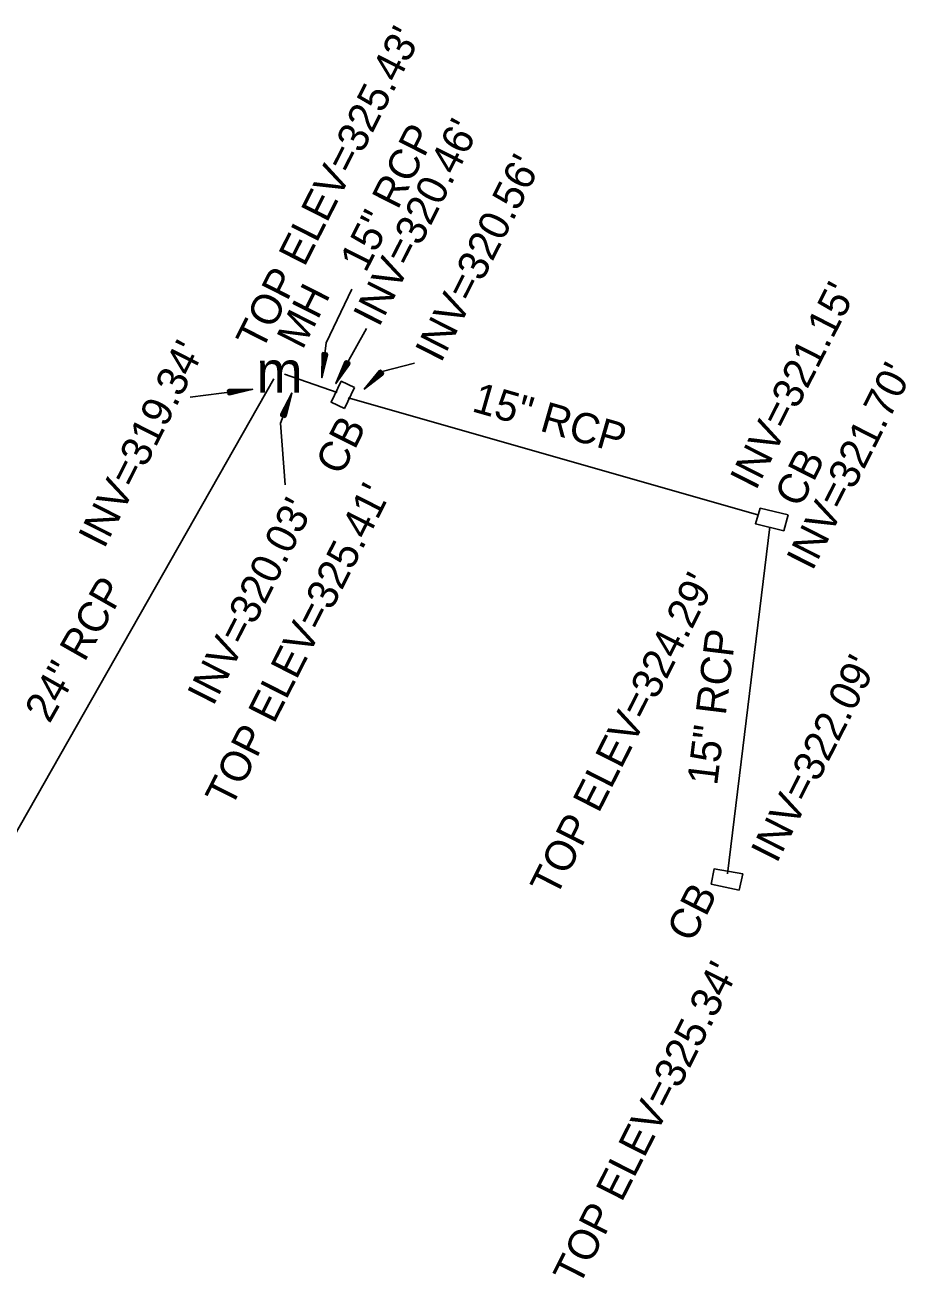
# Model space of a CAD drawing. Extents: x 1975859 to 1978323, y 778892 to 782836.
# Drawn here: x 1978206.4 to 1978322.9, y 782670.7 to 782836.1 of the extents above; entities that cross this region are included whole.
import ezdxf

# ---------------------------------------------------------------- set-up
doc = ezdxf.new("R2010")
doc.units = 0
for name, color, linetype in [('Exist Structure Minor Catch Basin', 7, 'Continuous'), ('Exist Structure Minor Catch Basin Text', 7, 'Continuous'), ('Exist Structure Minor Catch Basin Top Elevation', 7, 'Continuous'), ('Exist Structure Minor Pipes RCP 15 Inch', 7, 'Continuous'), ('Exist Structure Minor Pipes RCP 15 Inch Invert', 7, 'Continuous'), ('Exist Structure Minor Pipes RCP 15 Inch Text', 7, 'Continuous'), ('Exist Structure Minor Pipes RCP 24 Inch', 7, 'Continuous'), ('Exist Structure Minor Pipes RCP 24 Inch Invert', 7, 'Continuous'), ('Exist Structure Minor Pipes RCP 24 Inch Text', 7, 'Continuous'), ('Exist Structure Minor Storm Sewer Manhole CELL', 7, 'Continuous'), ('Exist Structure Minor Storm Sewer Manhole Text', 7, 'Continuous'), ('Exist Structure Minor Storm Sewer Manhole Top Elevation', 7, 'Continuous')]:
    doc.layers.add(name, color=color, linetype=linetype)

msp = doc.modelspace()

# ---------------------------------------------------------------- linework, layer by layer
at = {"layer": 'Exist Structure Minor Catch Basin'}
for p, q in [((1978249.95, 782788.25), (1978248.62, 782785.5)), ((1978307.23, 782771.45), (1978306.66, 782769.34)), ((1978297.06, 782722.69), (1978300.76, 782721.9))]:
    msp.add_line(p, q, dxfattribs=at)
for points in [[(1978249.95, 782788.25), (1978248.2, 782789.1), (1978246.87, 782786.32), (1978248.62, 782785.5)], [(1978306.66, 782769.34), (1978302.9, 782770.27), (1978303.54, 782772.33), (1978307.23, 782771.45)], [(1978300.76, 782721.9), (1978301.23, 782724.04), (1978297.44, 782724.71), (1978297.06, 782722.69)]]:
    msp.add_lwpolyline(points, dxfattribs=at)
at = {"layer": 'Exist Structure Minor Pipes RCP 15 Inch'}
for p, q in [((1978247.65, 782787.62), (1978240.69, 782790.04)), ((1978303.21, 782771.46), (1978249.13, 782786.92)), ((1978299.19, 782724.05), (1978304.79, 782769.85))]:
    msp.add_line(p, q, dxfattribs=at)
at = {"layer": 'Exist Structure Minor Pipes RCP 15 Inch Invert'}
for p, q in [((1978247.49, 782788.78), (1978251.52, 782796.05)), ((1978248.87, 782791.81), (1978249.33, 782791.55)), ((1978248.95, 782791.4), (1978248.89, 782791.74)), ((1978248.95, 782791.4), (1978248.96, 782791.76)), ((1978248.95, 782791.4), (1978249.05, 782791.71)), ((1978248.95, 782791.4), (1978249.15, 782791.65)), ((1978248.95, 782791.4), (1978249.23, 782791.6)), ((1978249.27, 782791.53), (1978248.95, 782791.4)), ((1978253.59, 782790.36), (1978257.88, 782791.49)), ((1978253.38, 782790.16), (1978253.43, 782790.51)), ((1978253.38, 782790.16), (1978253.5, 782790.5)), ((1978253.38, 782790.16), (1978253.57, 782790.42)), ((1978253.38, 782790.16), (1978253.65, 782790.34)), ((1978253.38, 782790.16), (1978253.71, 782790.28)), ((1978253.73, 782790.19), (1978253.38, 782790.16)), ((1978253.42, 782790.57), (1978253.8, 782790.19)), ((1978241.67, 782787.52), (1978240.17, 782783.57)), ((1978240.17, 782783.57), (1978240.78, 782775.43)), ((1978240.74, 782784.32), (1978240.24, 782784.51)), ((1978240.3, 782784.53), (1978240.61, 782784.71)), ((1978240.61, 782784.71), (1978240.36, 782784.47)), ((1978240.61, 782784.71), (1978240.44, 782784.43)), ((1978240.61, 782784.71), (1978240.55, 782784.39)), ((1978240.61, 782784.71), (1978240.71, 782784.38)), ((1978240.61, 782784.71), (1978240.65, 782784.36))]:
    msp.add_line(p, q, dxfattribs=at)
for points in [[(1978248.84, 782791.64), (1978247.49, 782788.78), (1978248.87, 782791.81), (1978248.89, 782791.74), (1978248.84, 782791.64), (1978248.95, 782791.4), (1978249.21, 782791.44), (1978249.27, 782791.53), (1978249.33, 782791.55), (1978247.49, 782788.78), (1978249.21, 782791.44)], [(1978248.87, 782791.81), (1978248.67, 782791.65), (1978247.49, 782788.78), (1978249.3, 782791.3), (1978249.33, 782791.55)], [(1978249.32, 782791.43), (1978247.49, 782788.78), (1978248.77, 782791.73)], [(1978247.59, 782788.92), (1978247.54, 782788.86), (1978247.57, 782788.95), (1978247.61, 782789.03), (1978247.58, 782788.94), (1978247.64, 782789), (1978247.69, 782789.08), (1978247.63, 782789.02), (1978247.65, 782789.11), (1978247.69, 782789.2), (1978247.68, 782789.1), (1978247.74, 782789.16), (1978247.79, 782789.24), (1978247.72, 782789.19), (1978247.73, 782789.28), (1978247.77, 782789.37), (1978247.77, 782789.27), (1978247.84, 782789.32), (1978247.89, 782789.4), (1978247.81, 782789.35), (1978247.81, 782789.45), (1978247.85, 782789.54), (1978247.86, 782789.43), (1978247.94, 782789.47), (1978247.99, 782789.55), (1978247.9, 782789.51), (1978247.89, 782789.62), (1978247.93, 782789.71), (1978247.95, 782789.6), (1978248.04, 782789.63), (1978248.09, 782789.71), (1978247.99, 782789.68), (1978247.97, 782789.79), (1978248.01, 782789.88), (1978248.04, 782789.76), (1978248.15, 782789.79), (1978248.2, 782789.87), (1978248.08, 782789.84), (1978248.05, 782789.96), (1978248.09, 782790.05), (1978248.13, 782789.92), (1978248.25, 782789.95), (1978248.3, 782790.02), (1978248.17, 782790.01), (1978248.13, 782790.13), (1978248.17, 782790.22), (1978248.22, 782790.09), (1978248.35, 782790.1), (1978248.4, 782790.18), (1978248.27, 782790.17), (1978248.21, 782790.3), (1978248.25, 782790.39), (1978248.31, 782790.25), (1978248.45, 782790.26), (1978248.5, 782790.34), (1978248.36, 782790.33), (1978248.29, 782790.47), (1978248.33, 782790.56), (1978248.4, 782790.41), (1978248.55, 782790.42), (1978248.6, 782790.5), (1978248.45, 782790.5), (1978248.37, 782790.64), (1978248.41, 782790.72), (1978248.49, 782790.58), (1978248.65, 782790.58), (1978248.7, 782790.65), (1978248.54, 782790.66), (1978248.45, 782790.81), (1978248.49, 782790.89), (1978248.57, 782790.75), (1978248.75, 782790.73), (1978248.8, 782790.81), (1978248.63, 782790.82), (1978248.53, 782790.98), (1978248.57, 782791.06), (1978248.67, 782790.91), (1978248.86, 782790.89), (1978248.91, 782790.97), (1978248.72, 782790.99), (1978248.61, 782791.15), (1978248.65, 782791.23), (1978248.76, 782791.07), (1978248.96, 782791.05), (1978249.01, 782791.13), (1978248.81, 782791.15), (1978248.69, 782791.32), (1978248.73, 782791.4), (1978248.85, 782791.23), (1978249.06, 782791.2), (1978249.11, 782791.28), (1978248.9, 782791.32), (1978248.77, 782791.49), (1978248.81, 782791.57), (1978248.95, 782791.4), (1978249.16, 782791.36)], [(1978253.36, 782790.42), (1978251.24, 782788.06), (1978253.42, 782790.57), (1978253.43, 782790.51), (1978253.36, 782790.42), (1978253.38, 782790.16), (1978253.65, 782790.12), (1978253.73, 782790.19), (1978253.8, 782790.19), (1978251.24, 782788.06), (1978253.65, 782790.12)], [(1978253.42, 782790.57), (1978253.2, 782790.48), (1978251.24, 782788.06), (1978253.7, 782789.96), (1978253.8, 782790.19)], [(1978253.75, 782790.08), (1978251.24, 782788.06), (1978253.31, 782790.52)], [(1978251.37, 782788.18), (1978251.31, 782788.13), (1978251.36, 782788.2), (1978251.43, 782788.27), (1978251.37, 782788.19), (1978251.44, 782788.24), (1978251.51, 782788.3), (1978251.44, 782788.26), (1978251.49, 782788.34), (1978251.55, 782788.41), (1978251.51, 782788.32), (1978251.59, 782788.36), (1978251.66, 782788.42), (1978251.57, 782788.39), (1978251.61, 782788.48), (1978251.68, 782788.55), (1978251.64, 782788.46), (1978251.73, 782788.48), (1978251.8, 782788.54), (1978251.71, 782788.52), (1978251.74, 782788.62), (1978251.8, 782788.69), (1978251.78, 782788.59), (1978251.87, 782788.6), (1978251.94, 782788.66), (1978251.84, 782788.65), (1978251.86, 782788.76), (1978251.93, 782788.83), (1978251.91, 782788.72), (1978252.01, 782788.72), (1978252.08, 782788.78), (1978251.98, 782788.78), (1978251.99, 782788.9), (1978252.05, 782788.97), (1978252.04, 782788.85), (1978252.15, 782788.85), (1978252.23, 782788.91), (1978252.11, 782788.91), (1978252.11, 782789.04), (1978252.18, 782789.11), (1978252.18, 782788.98), (1978252.3, 782788.97), (1978252.37, 782789.03), (1978252.24, 782789.04), (1978252.24, 782789.18), (1978252.3, 782789.25), (1978252.31, 782789.11), (1978252.44, 782789.09), (1978252.51, 782789.15), (1978252.38, 782789.18), (1978252.37, 782789.32), (1978252.43, 782789.39), (1978252.44, 782789.24), (1978252.58, 782789.21), (1978252.65, 782789.27), (1978252.51, 782789.31), (1978252.49, 782789.46), (1978252.55, 782789.53), (1978252.58, 782789.37), (1978252.72, 782789.33), (1978252.79, 782789.39), (1978252.65, 782789.44), (1978252.61, 782789.6), (1978252.68, 782789.67), (1978252.71, 782789.5), (1978252.87, 782789.45), (1978252.94, 782789.51), (1978252.78, 782789.57), (1978252.74, 782789.74), (1978252.8, 782789.81), (1978252.84, 782789.64), (1978253.01, 782789.58), (1978253.08, 782789.64), (1978252.91, 782789.7), (1978252.87, 782789.87), (1978252.93, 782789.94), (1978252.98, 782789.77), (1978253.15, 782789.7), (1978253.22, 782789.76), (1978253.05, 782789.83), (1978252.99, 782790.01), (1978253.05, 782790.08), (1978253.11, 782789.9), (1978253.29, 782789.82), (1978253.36, 782789.88), (1978253.18, 782789.96), (1978253.12, 782790.15), (1978253.18, 782790.22), (1978253.25, 782790.03), (1978253.43, 782789.94), (1978253.51, 782790), (1978253.31, 782790.09), (1978253.24, 782790.29), (1978253.3, 782790.36), (1978253.38, 782790.16), (1978253.58, 782790.06)], [(1978240.74, 782784.48), (1978241.67, 782787.52), (1978240.74, 782784.32), (1978240.71, 782784.38), (1978240.74, 782784.48), (1978240.61, 782784.71), (1978240.35, 782784.63), (1978240.3, 782784.53), (1978240.24, 782784.51), (1978241.67, 782787.52), (1978240.35, 782784.63)], [(1978240.74, 782784.32), (1978240.91, 782784.5), (1978241.67, 782787.52), (1978240.24, 782784.76), (1978240.24, 782784.51)], [(1978240.24, 782784.63), (1978241.67, 782787.52), (1978240.83, 782784.41)], [(1978241.6, 782787.36), (1978241.63, 782787.43), (1978241.61, 782787.34), (1978241.58, 782787.25), (1978241.6, 782787.34), (1978241.56, 782787.27), (1978241.52, 782787.19), (1978241.57, 782787.25), (1978241.56, 782787.16), (1978241.53, 782787.07), (1978241.53, 782787.17), (1978241.48, 782787.1), (1978241.44, 782787.02), (1978241.5, 782787.08), (1978241.5, 782786.98), (1978241.48, 782786.89), (1978241.47, 782786.99), (1978241.4, 782786.93), (1978241.36, 782786.85), (1978241.43, 782786.9), (1978241.45, 782786.8), (1978241.42, 782786.71), (1978241.4, 782786.82), (1978241.32, 782786.76), (1978241.28, 782786.68), (1978241.37, 782786.73), (1978241.39, 782786.62), (1978241.37, 782786.53), (1978241.34, 782786.64), (1978241.25, 782786.59), (1978241.21, 782786.51), (1978241.3, 782786.55), (1978241.34, 782786.44), (1978241.31, 782786.35), (1978241.27, 782786.46), (1978241.17, 782786.42), (1978241.13, 782786.34), (1978241.24, 782786.38), (1978241.28, 782786.26), (1978241.26, 782786.17), (1978241.2, 782786.29), (1978241.09, 782786.25), (1978241.05, 782786.17), (1978241.17, 782786.2), (1978241.23, 782786.08), (1978241.2, 782785.99), (1978241.14, 782786.11), (1978241.01, 782786.08), (1978240.97, 782785.99), (1978241.1, 782786.03), (1978241.17, 782785.9), (1978241.15, 782785.81), (1978241.07, 782785.94), (1978240.93, 782785.91), (1978240.89, 782785.82), (1978241.04, 782785.85), (1978241.12, 782785.73), (1978241.09, 782785.64), (1978241, 782785.76), (1978240.86, 782785.74), (1978240.82, 782785.65), (1978240.97, 782785.68), (1978241.06, 782785.55), (1978241.04, 782785.46), (1978240.94, 782785.59), (1978240.78, 782785.57), (1978240.74, 782785.48), (1978240.9, 782785.5), (1978241.01, 782785.37), (1978240.98, 782785.28), (1978240.88, 782785.41), (1978240.7, 782785.4), (1978240.66, 782785.31), (1978240.84, 782785.33), (1978240.96, 782785.19), (1978240.93, 782785.1), (1978240.8, 782785.24), (1978240.62, 782785.23), (1978240.58, 782785.14), (1978240.77, 782785.15), (1978240.9, 782785.01), (1978240.87, 782784.92), (1978240.74, 782785.06), (1978240.54, 782785.06), (1978240.51, 782784.97), (1978240.71, 782784.98), (1978240.85, 782784.83), (1978240.82, 782784.74), (1978240.67, 782784.89), (1978240.47, 782784.89), (1978240.43, 782784.8), (1978240.64, 782784.8), (1978240.79, 782784.65), (1978240.76, 782784.56), (1978240.61, 782784.71), (1978240.39, 782784.72)]]:
    msp.add_lwpolyline(points, dxfattribs=at)
at = {"layer": 'Exist Structure Minor Pipes RCP 15 Inch Text'}
for p, q in [((1978246.21, 782794.18), (1978249.6, 782801.24)), ((1978245.66, 782789.56), (1978246.21, 782794.18)), ((1978245.79, 782792.88), (1978246.32, 782792.82)), ((1978246.02, 782792.54), (1978245.83, 782792.83)), ((1978246.02, 782792.54), (1978245.89, 782792.87)), ((1978246.02, 782792.54), (1978246, 782792.86)), ((1978246.02, 782792.54), (1978246.11, 782792.85)), ((1978246.02, 782792.54), (1978246.2, 782792.83)), ((1978246.27, 782792.78), (1978246.02, 782792.54))]:
    msp.add_line(p, q, dxfattribs=at)
for points in [[(1978245.83, 782792.73), (1978245.66, 782789.56), (1978245.79, 782792.88), (1978245.83, 782792.83), (1978245.83, 782792.73), (1978246.02, 782792.54), (1978246.25, 782792.68), (1978246.27, 782792.78), (1978246.32, 782792.82), (1978245.66, 782789.56), (1978246.25, 782792.68)], [(1978245.79, 782792.88), (1978245.67, 782792.67), (1978245.66, 782789.56), (1978246.38, 782792.58), (1978246.32, 782792.82)], [(1978246.35, 782792.7), (1978245.66, 782789.56), (1978245.73, 782792.78)], [(1978245.69, 782789.73), (1978245.67, 782789.65), (1978245.67, 782789.75), (1978245.67, 782789.84), (1978245.68, 782789.75), (1978245.71, 782789.82), (1978245.72, 782789.92), (1978245.69, 782789.84), (1978245.68, 782789.93), (1978245.68, 782790.03), (1978245.7, 782789.93), (1978245.74, 782790.01), (1978245.76, 782790.1), (1978245.71, 782790.03), (1978245.69, 782790.12), (1978245.69, 782790.21), (1978245.72, 782790.12), (1978245.78, 782790.19), (1978245.79, 782790.28), (1978245.74, 782790.21), (1978245.7, 782790.31), (1978245.7, 782790.4), (1978245.75, 782790.3), (1978245.81, 782790.38), (1978245.83, 782790.47), (1978245.76, 782790.4), (1978245.71, 782790.49), (1978245.71, 782790.59), (1978245.77, 782790.49), (1978245.84, 782790.56), (1978245.86, 782790.65), (1978245.78, 782790.58), (1978245.72, 782790.68), (1978245.72, 782790.78), (1978245.79, 782790.68), (1978245.88, 782790.74), (1978245.9, 782790.83), (1978245.8, 782790.77), (1978245.73, 782790.87), (1978245.73, 782790.96), (1978245.81, 782790.86), (1978245.91, 782790.93), (1978245.93, 782791.02), (1978245.83, 782790.95), (1978245.74, 782791.06), (1978245.74, 782791.15), (1978245.84, 782791.05), (1978245.95, 782791.11), (1978245.97, 782791.2), (1978245.85, 782791.14), (1978245.75, 782791.24), (1978245.75, 782791.34), (1978245.86, 782791.23), (1978245.98, 782791.3), (1978246, 782791.39), (1978245.87, 782791.33), (1978245.76, 782791.43), (1978245.76, 782791.52), (1978245.88, 782791.42), (1978246.02, 782791.48), (1978246.04, 782791.57), (1978245.89, 782791.51), (1978245.77, 782791.62), (1978245.78, 782791.71), (1978245.9, 782791.61), (1978246.05, 782791.66), (1978246.07, 782791.76), (1978245.92, 782791.7), (1978245.78, 782791.8), (1978245.79, 782791.9), (1978245.92, 782791.79), (1978246.09, 782791.85), (1978246.11, 782791.94), (1978245.94, 782791.88), (1978245.79, 782791.99), (1978245.8, 782792.08), (1978245.95, 782791.98), (1978246.12, 782792.03), (1978246.14, 782792.12), (1978245.96, 782792.07), (1978245.8, 782792.18), (1978245.81, 782792.27), (1978245.97, 782792.16), (1978246.16, 782792.21), (1978246.18, 782792.31), (1978245.98, 782792.26), (1978245.81, 782792.36), (1978245.82, 782792.46), (1978245.99, 782792.35), (1978246.19, 782792.4), (1978246.21, 782792.49), (1978246.01, 782792.44), (1978245.82, 782792.55), (1978245.83, 782792.65), (1978246.02, 782792.54), (1978246.23, 782792.58)]]:
    msp.add_lwpolyline(points, dxfattribs=at)
at = {"layer": 'Exist Structure Minor Pipes RCP 24 Inch'}
msp.add_line((1978239.29, 782789.4), (1978195.95, 782713.16), dxfattribs=at)
msp.add_lwpolyline([(1978216.33, 782746.08), (1978216.33, 782746.08)], dxfattribs=at)
at = {"layer": 'Exist Structure Minor Pipes RCP 24 Inch Invert'}
for p, q in [((1978236.52, 782788.03), (1978228.23, 782787.01)), ((1978233.26, 782787.36), (1978233.2, 782787.89)), ((1978233.55, 782787.67), (1978233.21, 782787.77)), ((1978233.55, 782787.67), (1978233.22, 782787.69)), ((1978233.55, 782787.67), (1978233.24, 782787.57)), ((1978233.25, 782787.85), (1978233.55, 782787.67)), ((1978233.55, 782787.67), (1978233.25, 782787.47)), ((1978233.55, 782787.67), (1978233.3, 782787.42))]:
    msp.add_line(p, q, dxfattribs=at)
for points in [[(1978233.41, 782787.44), (1978236.52, 782788.03), (1978233.26, 782787.36), (1978233.3, 782787.42), (1978233.41, 782787.44), (1978233.55, 782787.67), (1978233.36, 782787.86), (1978233.25, 782787.85), (1978233.2, 782787.89), (1978236.52, 782788.03), (1978233.36, 782787.86)], [(1978233.26, 782787.36), (1978233.5, 782787.3), (1978236.52, 782788.03), (1978233.41, 782788.01), (1978233.2, 782787.89)], [(1978233.31, 782787.95), (1978236.52, 782788.03), (1978233.38, 782787.33)], [(1978236.35, 782788.02), (1978236.43, 782788.02), (1978236.34, 782788), (1978236.24, 782787.98), (1978236.33, 782788.01), (1978236.25, 782788.02), (1978236.16, 782788.01), (1978236.24, 782788), (1978236.15, 782787.96), (1978236.06, 782787.95), (1978236.15, 782787.99), (1978236.07, 782788.01), (1978235.97, 782788), (1978236.06, 782787.98), (1978235.97, 782787.93), (1978235.88, 782787.91), (1978235.96, 782787.97), (1978235.88, 782788), (1978235.79, 782787.99), (1978235.87, 782787.95), (1978235.78, 782787.89), (1978235.69, 782787.88), (1978235.78, 782787.94), (1978235.69, 782787.99), (1978235.6, 782787.98), (1978235.68, 782787.93), (1978235.6, 782787.86), (1978235.51, 782787.84), (1978235.59, 782787.92), (1978235.51, 782787.98), (1978235.41, 782787.97), (1978235.5, 782787.91), (1978235.42, 782787.82), (1978235.32, 782787.81), (1978235.41, 782787.9), (1978235.32, 782787.97), (1978235.23, 782787.96), (1978235.31, 782787.89), (1978235.23, 782787.79), (1978235.14, 782787.77), (1978235.22, 782787.87), (1978235.13, 782787.96), (1978235.04, 782787.95), (1978235.13, 782787.86), (1978235.05, 782787.75), (1978234.96, 782787.74), (1978235.03, 782787.85), (1978234.94, 782787.95), (1978234.85, 782787.94), (1978234.94, 782787.84), (1978234.86, 782787.72), (1978234.77, 782787.7), (1978234.85, 782787.83), (1978234.76, 782787.93), (1978234.66, 782787.93), (1978234.75, 782787.82), (1978234.68, 782787.68), (1978234.59, 782787.67), (1978234.66, 782787.81), (1978234.57, 782787.92), (1978234.48, 782787.92), (1978234.57, 782787.79), (1978234.5, 782787.65), (1978234.4, 782787.63), (1978234.48, 782787.78), (1978234.38, 782787.91), (1978234.29, 782787.91), (1978234.38, 782787.77), (1978234.31, 782787.61), (1978234.22, 782787.6), (1978234.29, 782787.75), (1978234.2, 782787.9), (1978234.1, 782787.9), (1978234.2, 782787.75), (1978234.13, 782787.58), (1978234.04, 782787.56), (1978234.1, 782787.74), (1978234.01, 782787.89), (1978233.92, 782787.89), (1978234.01, 782787.72), (1978233.95, 782787.54), (1978233.85, 782787.53), (1978233.92, 782787.71), (1978233.82, 782787.88), (1978233.73, 782787.88), (1978233.83, 782787.7), (1978233.76, 782787.51), (1978233.67, 782787.49), (1978233.73, 782787.69), (1978233.64, 782787.87), (1978233.54, 782787.87), (1978233.64, 782787.68), (1978233.58, 782787.47), (1978233.49, 782787.46), (1978233.55, 782787.67), (1978233.45, 782787.86)]]:
    msp.add_lwpolyline(points, dxfattribs=at)

# ---------------------------------------------------------------- texts
at = {"layer": 'Exist Structure Minor Catch Basin Text'}
for p in [(1978248.22, 782776.49), (1978308.82, 782772.23), (1978294.59, 782714.82)]:
    msp.add_text('CB', height=4, rotation=63.1198, dxfattribs=at).set_placement(p)
at = {"layer": 'Exist Structure Minor Catch Basin Top Elevation'}
for s, p in [("TOP ELEV=325.41'", (1978233.67, 782732.6)), ("TOP ELEV=324.29'", (1978276.55, 782720.81)), ("TOP ELEV=325.34'", (1978279.59, 782669.45))]:
    msp.add_text(s, height=4, rotation=63.1198, dxfattribs=at).set_placement(p)
at = {"layer": 'Exist Structure Minor Pipes RCP 15 Inch Invert'}
for s, p in [("INV=320.46'", (1978253.18, 782796.1)), ("INV=320.56'", (1978261.36, 782791.4)), ("INV=321.15'", (1978302.94, 782774.55)), ("INV=321.70'", (1978310.4, 782763.92)), ("INV=320.03'", (1978231.29, 782746.07)), ("INV=322.09'", (1978305.7, 782725.31))]:
    msp.add_text(s, height=4, rotation=63.1198, dxfattribs=at).set_placement(p)
at = {"layer": 'Exist Structure Minor Pipes RCP 15 Inch Text'}
for rotation, p in [(63.1198, (1978251.43, 782803.3)), (344.0407, (1978265.3, 782785.16)), (83.0273, (1978297.83, 782735.62))]:
    msp.add_text('15" RCP', height=4, rotation=rotation, dxfattribs=at).set_placement(p)
at = {"layer": 'Exist Structure Minor Pipes RCP 24 Inch Invert'}
msp.add_text("INV=319.34'", height=4, rotation=63.1198, dxfattribs=at).set_placement((1978216.88, 782766.84))
at = {"layer": 'Exist Structure Minor Pipes RCP 24 Inch Text'}
msp.add_text('24" RCP', height=4, rotation=60.3792, dxfattribs=at).set_placement((1978209.68, 782743.79))
at = {"layer": 'Exist Structure Minor Storm Sewer Manhole CELL'}
msp.add_text('m', height=5.5, dxfattribs=at).set_placement((1978236.99, 782787.6))
at = {"layer": 'Exist Structure Minor Storm Sewer Manhole Text'}
msp.add_text('MH', height=4, rotation=63.1198, dxfattribs=at).set_placement((1978243.08, 782793.14))
at = {"layer": 'Exist Structure Minor Storm Sewer Manhole Top Elevation'}
msp.add_text("TOP ELEV=325.43'", height=4, rotation=63.1198, dxfattribs=at).set_placement((1978237.7, 782792.94))

doc.saveas('drawing.dxf')
